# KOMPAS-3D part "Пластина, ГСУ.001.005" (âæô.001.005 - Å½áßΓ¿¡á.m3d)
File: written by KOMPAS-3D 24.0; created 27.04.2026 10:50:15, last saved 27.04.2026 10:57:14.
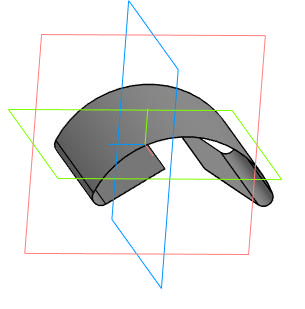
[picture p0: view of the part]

Document properties: Автор: User7; Полное имя файла: C:\Users\User7\Desktop\Двигатель мясорубки\ГСУ.001.005 - Пластина.m3d

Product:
- Part/product: Пластина  | designation ГСУ.001.005
    Масса: 0.002713

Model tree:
1. Эскиз:1
2. Листовое тело:1
     Расстояние 1 = 38; Толщина листового тела = 0.1; Радиус сгиба = 2; Коэффициент = 0.4; Величина сгиба = 10; Радиус сгиба = 21.9279; Коэффициент = 0.4; Величина сгиба = 10; Радиус сгиба = 2; Коэффициент = 0.4; Величина сгиба = 10

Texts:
  ГСУ.001.005
  Угловой размер с обрывом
